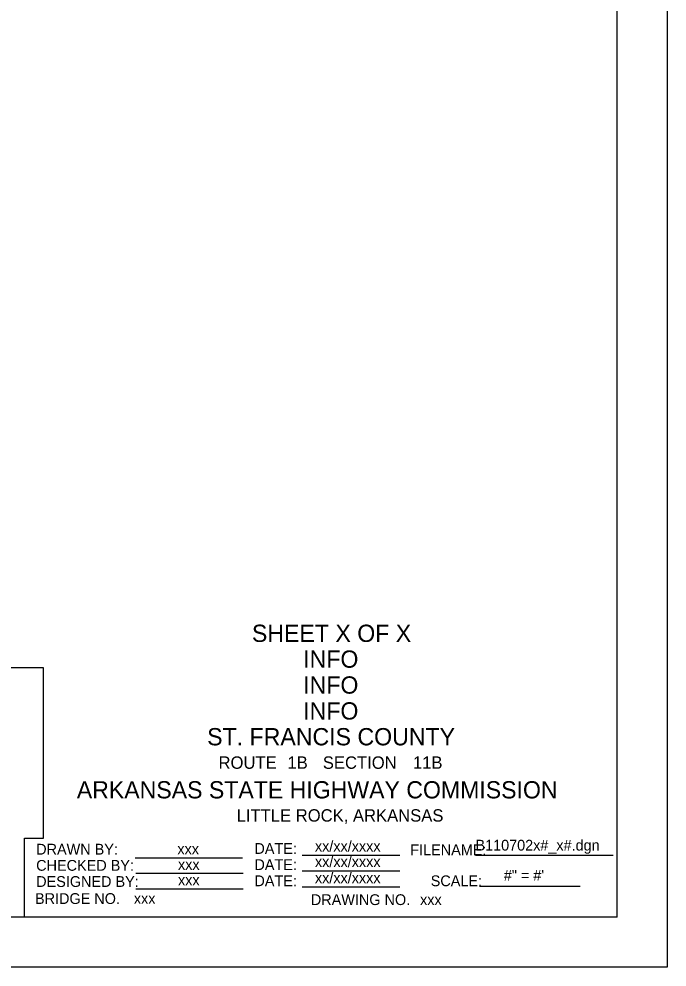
# Model space of a CAD drawing. Extents: x 16 to 1228740, y 11 to 152440.
# Drawn here: x 17.864 to 18.49, y 10.709 to 11.626 of the extents above; entities that cross this region are included whole.
import ezdxf

# ---------------------------------------------------------------- set-up
doc = ezdxf.new("R2010")
doc.units = 0
for name, color, linetype in [('B_Copy In', 7, 'Continuous'), ('B_County and Route', 7, 'Continuous'), ('B_Text', 7, 'Continuous'), ('B_Title Text', 7, 'Continuous'), ('R_Border', 7, 'Continuous'), ('R_No Plot', 7, 'Continuous')]:
    doc.layers.add(name, color=color, linetype=linetype)

msp = doc.modelspace()

# ---------------------------------------------------------------- linework, layer by layer
at = {"layer": 'B_Text'}
for p, q in [((18.13771, 10.81765), (18.23221, 10.81765)), ((18.30529, 10.81765), (18.43835, 10.81765)), ((17.97661, 10.81515), (18.08021, 10.81515)), ((17.97721, 10.80015), (18.08081, 10.80015)), ((18.13771, 10.80265), (18.23221, 10.80265)), ((18.13771, 10.80265), (18.23221, 10.80265)), ((17.97721, 10.78515), (18.08081, 10.78515)), ((18.13771, 10.78703), (18.23221, 10.78703)), ((18.30917, 10.78765), (18.40631, 10.78765))]:
    msp.add_line(p, q, dxfattribs=at)
at = {"layer": 'R_Border'}
for q in [(18.44221, 12.49475), (15.78327, 10.75755)]:
    msp.add_line((18.44221, 10.75755), q, dxfattribs=at)
msp.add_lwpolyline([(15.65694, 12.54282), (18.49027, 12.54282), (18.49027, 10.70949), (15.65694, 10.70949)], close=True, dxfattribs=at)
at = {"layer": 'R_No Plot'}
for p, q in [((17.888, 10.99864), (17.47349, 10.99864)), ((17.888, 10.83424), (17.888, 10.99864)), ((17.86946, 10.83424), (17.888, 10.83424)), ((17.86946, 10.75755), (17.86946, 10.83424))]:
    msp.add_line(p, q, dxfattribs=at)

# ---------------------------------------------------------------- texts
at = {"layer": 'B_Copy In'}
for s, height, p in [('SHEET X OF X', 0.0167, (18.08929, 11.02383)), ('INFO', 0.0167, (18.13883, 10.99888)), ('INFO', 0.0167, (18.13883, 10.97383)), ('INFO', 0.0167, (18.13883, 10.94878)), ('xxx', 0.0104, (18.0173, 10.81846)), ('xx/xx/xxxx', 0.0104, (18.15019, 10.82119)), ('B110702x#_x#.dgn', 0.0104, (18.30529, 10.8221)), ('xx/xx/xxxx', 0.0104, (18.15019, 10.80619)), ('xxx', 0.0104, (18.0179, 10.80346)), ('xx/xx/xxxx', 0.0104, (18.15019, 10.79057)), ('#" = #\'', 0.0104, (18.33262, 10.79302)), ('xxx', 0.0104, (18.0179, 10.78846)), ('xxx', 0.010417, (17.97523, 10.7706)), ('xxx', 0.010417, (18.25173, 10.76944))]:
    msp.add_text(s, height=height, dxfattribs=at).set_placement(p)
at = {"layer": 'B_County and Route'}
for s, height, p in [('ST. FRANCIS COUNTY', 0.0167, (18.04607, 10.92383)), ('1B', 0.012, (18.12362, 10.90115)), ('11B', 0.012, (18.24485, 10.90115))]:
    msp.add_text(s, height=height, dxfattribs=at).set_placement(p)
at = {"layer": 'B_Text'}
for s, height, p in [('DRAWN BY:', 0.010417, (17.88091, 10.8182)), ('DATE:', 0.010417, (18.09171, 10.8189)), ('FILENAME:', 0.010417, (18.24229, 10.81765)), ('CHECKED BY:', 0.0104166, (17.88091, 10.80257)), ('DATE:', 0.010417, (18.09171, 10.80328)), ('DESIGNED BY:', 0.0104166, (17.88091, 10.78695)), ('DATE:', 0.010417, (18.09171, 10.78765)), ('SCALE:', 0.010417, (18.26201, 10.78765)), ('BRIDGE NO.', 0.010417, (17.87978, 10.77048)), ('DRAWING NO.', 0.0104166, (18.14623, 10.76942))]:
    msp.add_text(s, height=height, dxfattribs=at).set_placement(p)
at = {"layer": 'B_Title Text'}
for s, height, p in [('ROUTE          SECTION ', 0.012, (18.05705, 10.90115)), ('ARKANSAS STATE HIGHWAY COMMISSION', 0.0166667, (17.92017, 10.87252)), ('LITTLE ROCK, ARKANSAS', 0.012, (18.07454, 10.85007))]:
    msp.add_text(s, height=height, dxfattribs=at).set_placement(p)

doc.saveas('drawing.dxf')
